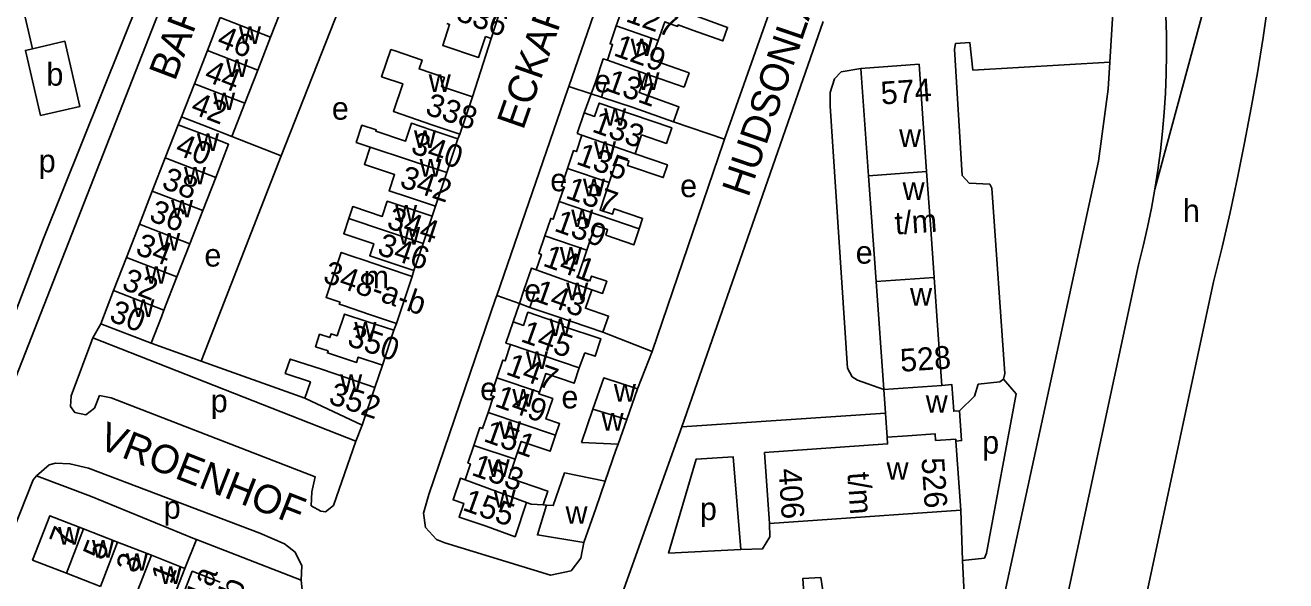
# Model space of a CAD drawing. Extents: x 159294 to 161936, y 384538 to 386517.
# Drawn here: x 161615.6 to 161836.9, y 385101 to 385198.5 of the extents above; entities that cross this region are included whole.
import ezdxf

# ---------------------------------------------------------------- set-up
doc = ezdxf.new("R2010")
doc.units = 0
for name, color, linetype in [('BLT_Basislijn', 7, 'Continuous'), ('BLT_Bebouwing', 7, 'Continuous'), ('BLT_Centroide', 7, 'Continuous'), ('BLT_Huisnummer', 7, 'Continuous'), ('BLT_Huisnummer_ tussenligend', 7, 'Continuous'), ('BLT_Huisnummer_reeks', 7, 'Continuous'), ('BLT_Onderdoorgang_en_onderverdeling', 7, 'Continuous'), ('BLT_Onderverdeling_panden', 7, 'Continuous'), ('BLT_Straatnaam', 7, 'Continuous'), ('BLT_Vlakafsluiter', 7, 'Continuous')]:
    doc.layers.add(name, color=color, linetype=linetype)

msp = doc.modelspace()

# ---------------------------------------------------------------- linework, layer by layer
at = {"layer": 'BLT_Basislijn'}
for p, q in [((161679.62, 385224.05), (161660.57, 385175.55)), ((161723.4, 385223.71), (161711.03, 385187.71)), ((161628.12, 385172.88), (161646.48, 385219.73)), ((161618.85, 385161.07), (161637.25, 385206.88)), ((161806.91, 385207.1), (161805.99, 385191.99)), ((161738.36, 385178.48), (161747.52, 385204.43)), ((161615.25, 385201.44), (161616.9, 385194.35)), ((161730.86, 385128.01), (161755.69, 385199.14)), ((161697.38, 385196.17), (161694.12, 385185.9)), ((161714.96, 385186.44), (161715.77, 385188.68)), ((161711.03, 385187.71), (161714.96, 385186.44)), ((161713.74, 385183.09), (161714.96, 385186.44)), ((161714.96, 385186.44), (161716.76, 385185.86)), ((161642.48, 385181.03), (161643.08, 385182.43)), ((161729.43, 385181.55), (161738.36, 385178.48)), ((161691.91, 385179.37), (161691.58, 385178.55)), ((161651.92, 385178.98), (161660.57, 385175.55)), ((161660.57, 385175.55), (161646.54, 385139.52)), ((161613.46, 385135.38), (161628.12, 385172.88)), ((161687.05, 385164.95), (161687.62, 385166.71)), ((161608.36, 385133.7), (161618.85, 385161.07)), ((161683.85, 385155.42), (161683.57, 385154.36)), ((161794.16, 385077.96), (161811, 385156.43)), ((161702.37, 385149.64), (161698.38, 385151.08)), ((161702.37, 385149.64), (161703.16, 385151.98)), ((161701.27, 385146.42), (161702.37, 385149.64)), ((161704.22, 385148.97), (161702.37, 385149.64)), ((161628.88, 385146.1), (161627.48, 385143.62)), ((161680.35, 385144.95), (161680.77, 385146.12)), ((161717.03, 385144.6), (161725.66, 385141.21)), ((161627.48, 385143.62), (161673.67, 385125.47)), ((161646.54, 385139.52), (161637.73, 385142.66)), ((161664.71, 385133.06), (161646.54, 385139.52)), ((161676.99, 385134.92), (161678.35, 385138.84)), ((161730.86, 385128.01), (161766.6, 385130.41)), ((161674.74, 385128.31), (161673.67, 385125.47)), ((161719.31, 385123.93), (161719.72, 385124.95)), ((161779.81, 385113.36), (161780.14, 385104.58)), ((161643.64, 385103.13), (161645.67, 385108.25)), ((161645.67, 385108.25), (161664.09, 385101.11)), ((161664.09, 385101.11), (161664.48, 385097.1))]:
    msp.add_line(p, q, dxfattribs=at)
for points in [[(161824.2, 385153.45), (161825.67, 385159.53), (161827.07, 385165.62), (161828.39, 385171.72), (161829.62, 385177.85), (161830.79, 385183.99), (161831.87, 385190.14), (161832.87, 385196.31), (161833.79, 385202.49), (161834.64, 385208.68), (161835.4, 385214.88), (161836.09, 385221.09), (161836.69, 385227.31), (161836.86, 385229.15)], [(161813.9, 385169.7), (161814.43, 385173.06), (161814.88, 385176.43), (161815.25, 385179.81), (161815.54, 385183.19), (161815.75, 385186.58), (161815.88, 385189.98), (161815.93, 385193.38), (161815.9, 385196.77), (161815.79, 385200.17), (161815.74, 385201.24)], [(161787.31, 385136.37), (161787.53, 385137.34), (161785.28, 385169.87), (161784.9, 385170.58), (161781.3, 385170.77), (161780.09, 385172.13), (161778.74, 385194.28), (161778.91, 385195.28), (161781.43, 385195.45), (161781.94, 385190.61), (161805.99, 385191.99)], [(161762.3, 385190.91), (161758.81, 385190.3), (161757.68, 385189.08), (161756.88, 385186.69), (161756.89, 385184.27), (161759.92, 385138.33)], [(161762.65, 384984.06), (161803.97, 385174.65), (161805.7, 385187.28), (161805.99, 385191.99)], [(161698.38, 385151.08), (161710.88, 385187.27), (161711.03, 385187.71)], [(161738.36, 385178.48), (161738.18, 385177.95), (161725.66, 385141.21)], [(161811, 385156.43), (161811.84, 385159.73), (161812.61, 385163.04), (161813.29, 385166.36), (161813.9, 385169.7)], [(161796.66, 385024.4), (161812.3, 385097.98), (161824.2, 385153.45)], [(161713.65, 385107.71), (161713.17, 385104.94), (161711.42, 385102.71), (161707.83, 385101.95), (161689.26, 385107.64), (161687.83, 385108.22), (161685.87, 385110.36), (161685.54, 385112.86), (161686.46, 385116.15), (161698.17, 385150.46), (161698.38, 385151.08)], [(161627.48, 385143.62), (161623.69, 385133.43), (161623.56, 385131.55), (161624.33, 385130.54), (161626.29, 385130.1), (161627.78, 385131.27), (161628.68, 385133.49), (161630.73, 385133.07), (161666.52, 385119.25), (161665.93, 385116.59), (161665.82, 385114.15), (161667.5, 385113.2), (161668.33, 385113.1), (161669.76, 385114.23), (161673.67, 385125.47)], [(161725.66, 385141.21), (161723.09, 385134.7)], [(161759.92, 385138.33), (161760.78, 385136.81), (161761.67, 385136.17), (161766.31, 385134.54)], [(161779.59, 385130.81), (161782.25, 385133.4), (161782.89, 385135.47), (161786.68, 385135.89), (161787.31, 385136.37)], [(161780.14, 385104.58), (161783.97, 385104.97), (161784.34, 385105.82), (161789.56, 385133.79), (161787.31, 385136.37)], [(161730.86, 385128.01), (161719.85, 385097.24), (161716.35, 385083.92), (161705.65, 385033.01)], [(161719.31, 385123.93), (161717.42, 385118.49)], [(161741.25, 385106.46), (161739.87, 385122.75), (161733.38, 385122.32), (161728.55, 385105.86), (161741.25, 385106.46)], [(161617.59, 385119.41), (161619.86, 385121.35), (161620.95, 385121.61), (161623.49, 385121.54), (161626.76, 385120.78), (161656.79, 385109.37), (161661.11, 385107.48), (161662.99, 385106.02), (161664.16, 385103.64), (161664.09, 385101.11)], [(161607.82, 385095.65), (161617.01, 385118.7), (161617.59, 385119.41)], [(161645.67, 385108.25), (161645.37, 385108.37), (161627.09, 385115.85), (161617.59, 385119.41)], [(161706.53, 385114.31), (161707.14, 385114.28)], [(161741.25, 385106.46), (161745.04, 385106.61), (161746.29, 385108.73), (161746.26, 385111.04)], [(161752.52, 385095.33), (161752.11, 385101.41), (161755.25, 385101.54), (161755.95, 385096.94), (161780.13, 385098.66), (161780.4, 385098.74), (161780.14, 385104.58)]]:
    msp.add_lwpolyline(points, dxfattribs=at)
at = {"layer": 'BLT_Bebouwing'}
for p, q in [((161660.95, 385202.18), (161658.69, 385196.38)), ((161699.18, 385201.59), (161697.38, 385196.17)), ((161649.87, 385199.82), (161647.6, 385194.02)), ((161658.69, 385196.38), (161656.43, 385190.58)), ((161647.6, 385194.02), (161645.34, 385188.22)), ((161656.43, 385190.58), (161654.18, 385184.78)), ((161763.64, 385172.08), (161762.3, 385190.91)), ((161645.34, 385188.22), (161643.08, 385182.43)), ((161724.55, 385189.98), (161731.25, 385187.64)), ((161694.12, 385185.9), (161691.91, 385179.37)), ((161654.18, 385184.78), (161651.92, 385178.98)), ((161713.74, 385183.09), (161712.51, 385179.48)), ((161773.82, 385172.8), (161773.17, 385182.09)), ((161642.48, 385181.03), (161640.21, 385175.21)), ((161712.51, 385179.48), (161713.34, 385179.2)), ((161691.58, 385178.55), (161689.6, 385172.63)), ((161640.21, 385175.21), (161637.94, 385169.39)), ((161689.6, 385172.63), (161687.62, 385166.71)), ((161774.48, 385163.51), (161773.82, 385172.8)), ((161646.8, 385165.94), (161649.06, 385171.77)), ((161764.96, 385153.52), (161763.64, 385172.08)), ((161637.94, 385169.39), (161635.68, 385163.57)), ((161644.53, 385160.12), (161646.8, 385165.94)), ((161687.05, 385164.95), (161685.45, 385160.18)), ((161635.68, 385163.57), (161633.41, 385157.74)), ((161775.13, 385154.24), (161774.48, 385163.51)), ((161642.26, 385154.3), (161644.53, 385160.12)), ((161685.45, 385160.18), (161683.85, 385155.42)), ((161633.41, 385157.74), (161631.14, 385151.92)), ((161639.99, 385148.48), (161642.26, 385154.3)), ((161683.57, 385154.36), (161680.77, 385146.12)), ((161764.96, 385153.52), (161766.31, 385134.54)), ((161775.78, 385144.98), (161775.13, 385154.24)), ((161631.14, 385151.92), (161628.88, 385146.1)), ((161628.88, 385146.1), (161637.73, 385142.66)), ((161680.35, 385144.95), (161678.35, 385138.84)), ((161776.47, 385135.28), (161775.78, 385144.98)), ((161674.74, 385128.31), (161664.71, 385133.06)), ((161676.99, 385134.92), (161674.74, 385128.31)), ((161721.23, 385129.31), (161723.09, 385134.7)), ((161766.31, 385134.54), (161766.6, 385130.41)), ((161719.72, 385124.95), (161721.23, 385129.31)), ((161713.24, 385125.28), (161719.72, 385124.95)), ((161779.81, 385113.36), (161778.96, 385125.51)), ((161745.39, 385123.53), (161746.26, 385111.04)), ((161715.77, 385113.69), (161717.42, 385118.49)), ((161713.65, 385107.71), (161715.77, 385113.69)), ((161771.42, 385112.78), (161779.81, 385113.36)), ((161746.26, 385111.04), (161754.65, 385111.62)), ((161754.65, 385111.62), (161763.03, 385112.2)), ((161763.03, 385112.2), (161771.42, 385112.78)), ((161631.83, 385107.77), (161625.89, 385110.08)), ((161637.77, 385105.47), (161631.83, 385107.77)), ((161643.64, 385103.13), (161637.77, 385105.47)), ((161622.88, 385102.32), (161628.82, 385100.01)), ((161639.51, 385092.59), (161643.64, 385103.13))]:
    msp.add_line(p, q, dxfattribs=at)
for points in [[(161721.94, 385204.14), (161720.93, 385201.32), (161720.45, 385201.49), (161719.36, 385198.36)], [(161726.69, 385195.81), (161727.86, 385199.08), (161730.11, 385198.28), (161730.2, 385198.53), (161732.76, 385197.62), (161738.06, 385195.73), (161738.9, 385198.1), (161733.61, 385199.99)], [(161696.42, 385196.48), (161695.21, 385192.83), (161688.9, 385194.91), (161690.12, 385198.62), (161689.65, 385198.76)], [(161719.36, 385198.36), (161718.27, 385195.24), (161718.71, 385195.09), (161717.8, 385192.33)], [(161616.9, 385194.35), (161622.61, 385195.66), (161625.23, 385184.24), (161618.29, 385182.65)], [(161697.38, 385196.17), (161696.79, 385196.36), (161696.42, 385196.48)], [(161731.25, 385187.64), (161732.14, 385190.11), (161725.5, 385192.48), (161726.69, 385195.81)], [(161618.29, 385182.65), (161615.67, 385194.07), (161616.9, 385194.35)], [(161694.12, 385185.9), (161688.68, 385187.74), (161689.21, 385189.31), (161684.76, 385190.82), (161685.29, 385192.36), (161680.55, 385193.96), (161679.8, 385194.22), (161678.19, 385189.45), (161681.89, 385188.2), (161680.24, 385183.35), (161687.17, 385180.97), (161691.91, 385179.37)], [(161717.8, 385192.33), (161717.05, 385192.57), (161715.77, 385188.68)], [(161773.17, 385182.09), (161772.5, 385191.63), (161762.3, 385190.91)], [(161715.77, 385188.68), (161717.5, 385188.11), (161716.76, 385185.86)], [(161729.43, 385181.55), (161730.37, 385184.14), (161723.36, 385186.7), (161724.55, 385189.98)], [(161716.76, 385185.86), (161722.35, 385184.04), (161729.43, 385181.55)], [(161722.67, 385175.9), (161723.81, 385179.23), (161728.15, 385177.75), (161729.09, 385180.49), (161722.03, 385182.89), (161716.37, 385184.82), (161715.56, 385182.47), (161713.74, 385183.09)], [(161643.08, 385182.43), (161647.74, 385180.61), (161651.92, 385178.98)], [(161649.06, 385171.77), (161651.33, 385177.59), (161647.14, 385179.22), (161642.48, 385181.03)], [(161676.18, 385177.11), (161673.73, 385177.93), (161674.73, 385180.94), (161677.25, 385180.1), (161677.18, 385179.87), (161682.38, 385178.14), (161683.42, 385181.28), (161686.84, 385180.14), (161691.58, 385178.55)], [(161687.62, 385166.71), (161682.88, 385168.29), (161679.5, 385169.42), (161680.45, 385172.28), (161675.16, 385174.05), (161676.18, 385177.11)], [(161713.34, 385179.2), (161712.36, 385176.31), (161711.88, 385176.47), (161710.82, 385173.34)], [(161718.11, 385170.86), (161719.63, 385175.33), (161721.58, 385174.67), (161721.31, 385173.88), (161727.6, 385171.75), (161728.35, 385173.97), (161722.67, 385175.9)], [(161710.82, 385173.34), (161709.75, 385170.22), (161710.23, 385170.06), (161709.37, 385167.55)], [(161723.38, 385162.78), (161723.99, 385164.57), (161719.02, 385166.27), (161718.69, 385165.3), (161716.53, 385166.04), (161718.11, 385170.86)], [(161672.42, 385164.56), (161673.13, 385166.66), (161678.28, 385164.93), (161679.18, 385167.59), (161682.31, 385166.54), (161687.05, 385164.95)], [(161709.37, 385167.55), (161708.31, 385164.43), (161707.85, 385164.58), (161706.8, 385161.51)], [(161683.85, 385155.42), (161679.11, 385157.01), (161676.09, 385158.02), (161676.79, 385160.12), (161671.53, 385161.89), (161672.42, 385164.56)], [(161714.17, 385159), (161715.66, 385163.35), (161717.85, 385162.61), (161717.51, 385161.62)], [(161717.51, 385161.62), (161722.44, 385159.94), (161723.38, 385162.78)], [(161706.8, 385161.51), (161705.76, 385158.43), (161706.23, 385158.27), (161705.31, 385155.55)], [(161683.57, 385154.36), (161678.84, 385155.97), (161674.95, 385157.29), (161673.11, 385157.92), (161671.11, 385158.6), (161668.43, 385150.71), (161670.88, 385149.87), (161670.76, 385149.52), (161671.48, 385149.28), (161676.04, 385147.73), (161680.77, 385146.12)], [(161715.05, 385152.06), (161716.95, 385151.41), (161717.68, 385153.55), (161715.02, 385154.46), (161714.73, 385153.6), (161712.59, 385154.33), (161714.17, 385159)], [(161705.31, 385155.55), (161704.48, 385155.84), (161703.16, 385151.98)], [(161703.16, 385151.98), (161705.03, 385151.34), (161704.22, 385148.97)], [(161717.03, 385144.6), (161718, 385147.45), (161713.94, 385148.83), (161715.05, 385152.06)], [(161637.73, 385142.66), (161639.54, 385147.32), (161639.99, 385148.48)], [(161704.22, 385148.97), (161708.95, 385147.35), (161717.03, 385144.6)], [(161678.35, 385138.84), (161674.09, 385140.24), (161673.79, 385139.31), (161669.04, 385140.87), (161668.68, 385140.99), (161668.79, 385141.32), (161666.59, 385142.05), (161667.31, 385144.24), (161669.1, 385143.66), (161669.32, 385144.33), (161670.4, 385143.98), (161671.65, 385147.8), (161675.6, 385146.51), (161680.35, 385144.95)], [(161701.27, 385146.42), (161700.01, 385142.7), (161700.81, 385142.43)], [(161712.88, 385138.35), (161713.86, 385140.97), (161715.63, 385140.38), (161716.66, 385143.43), (161709.94, 385145.7), (161710.04, 385146.02), (161708.6, 385146.51), (161703.86, 385148.11), (161703.08, 385145.81), (161701.27, 385146.42)], [(161700.81, 385142.43), (161699.84, 385139.57), (161699.43, 385139.71), (161698.38, 385136.61)], [(161664.71, 385133.06), (161665.68, 385135.88), (161661.28, 385137.38), (161662.14, 385139.91), (161667.62, 385138.11), (161672.26, 385136.53), (161676.99, 385134.92)], [(161705.88, 385134.08), (161706.98, 385137.35), (161711.96, 385135.66), (161712.88, 385138.35)], [(161698.38, 385136.61), (161697.34, 385133.52), (161697.82, 385133.36), (161696.86, 385130.53)], [(161723.09, 385134.7), (161717.17, 385136.59), (161715.26, 385131.1)], [(161779.59, 385130.81), (161778.59, 385130.74), (161778.26, 385135.41), (161776.47, 385135.28)], [(161708.72, 385126.52), (161709.42, 385128.58), (161707.02, 385129.39), (161708.22, 385132.95), (161705.78, 385133.78), (161705.88, 385134.08)], [(161715.26, 385131.1), (161713.24, 385125.28)], [(161778.96, 385125.51), (161779.96, 385125.58), (161779.59, 385130.81)], [(161696.86, 385130.53), (161695.91, 385127.7), (161695.43, 385127.87), (161694.38, 385124.76)], [(161766.6, 385130.41), (161766.9, 385126.2)], [(161701.62, 385122.31), (161702.68, 385125.46), (161707.78, 385123.73), (161708.72, 385126.52)], [(161766.9, 385126.2), (161766.99, 385125.02), (161745.39, 385123.53)], [(161694.38, 385124.76), (161693.33, 385121.64), (161693.77, 385121.5), (161692.83, 385118.71)], [(161706.53, 385114.31), (161707.35, 385116.73), (161700.51, 385119.04), (161701.62, 385122.31)], [(161707.14, 385114.28), (161708.31, 385114.2), (161710.25, 385119.92), (161717.42, 385118.49)], [(161692.83, 385118.71), (161692, 385118.99), (161690.72, 385115.2), (161692.59, 385114.57), (161691.78, 385112.18), (161696.52, 385110.58), (161701.6, 385108.72), (161703.62, 385114.75)], [(161703.62, 385114.75), (161704.41, 385114.45), (161706.53, 385114.31)], [(161707.14, 385114.28), (161705.51, 385109.05), (161713.65, 385107.71)], [(161625.89, 385110.08), (161619.96, 385112.39), (161616.94, 385104.63), (161622.88, 385102.32)], [(161649.84, 385100.73), (161644.94, 385102.67), (161642.24, 385095.7), (161647.1, 385093.79)]]:
    msp.add_lwpolyline(points, dxfattribs=at)
at = {"layer": 'BLT_Onderdoorgang_en_onderverdeling'}
for p, q in [((161766.31, 385134.54), (161776.47, 385135.28)), ((161778.96, 385125.51), (161778.94, 385125.85))]:
    msp.add_line(p, q, dxfattribs=at)
msp.add_lwpolyline([(161778.94, 385125.85), (161775.39, 385125.61), (161775.31, 385126.79), (161770.47, 385126.45)], dxfattribs=at)
at = {"layer": 'BLT_Onderverdeling_panden'}
for p, q in [((161658.69, 385196.38), (161649.87, 385199.82)), ((161719.36, 385198.36), (161726.69, 385195.81)), ((161656.43, 385190.58), (161647.6, 385194.02)), ((161717.8, 385192.33), (161724.55, 385189.98)), ((161654.18, 385184.78), (161645.34, 385188.22)), ((161689.6, 385172.63), (161676.18, 385177.11)), ((161713.34, 385179.2), (161722.67, 385175.9)), ((161649.06, 385171.77), (161640.21, 385175.21)), ((161710.82, 385173.34), (161718.11, 385170.86)), ((161763.64, 385172.08), (161773.82, 385172.8)), ((161646.8, 385165.94), (161637.94, 385169.39)), ((161709.37, 385167.55), (161723.38, 385162.78)), ((161685.45, 385160.18), (161672.42, 385164.56)), ((161644.53, 385160.12), (161635.68, 385163.57)), ((161706.8, 385161.51), (161714.17, 385159)), ((161642.26, 385154.3), (161633.41, 385157.74)), ((161705.31, 385155.55), (161715.05, 385152.06)), ((161764.96, 385153.52), (161775.13, 385154.24)), ((161639.99, 385148.48), (161631.14, 385151.92)), ((161700.81, 385142.43), (161712.88, 385138.35)), ((161698.38, 385136.61), (161705.88, 385134.08)), ((161715.26, 385131.1), (161721.23, 385129.31)), ((161696.86, 385130.53), (161708.72, 385126.52)), ((161770.47, 385126.45), (161766.9, 385126.2)), ((161694.38, 385124.76), (161701.62, 385122.31)), ((161692.83, 385118.71), (161703.62, 385114.75)), ((161622.88, 385102.32), (161625.89, 385110.08)), ((161628.82, 385100.01), (161631.83, 385107.77)), ((161634.76, 385097.71), (161637.77, 385105.47))]:
    msp.add_line(p, q, dxfattribs=at)
at = {"layer": 'BLT_Vlakafsluiter'}
msp.add_lwpolyline([(161822.78, 385203.09), (161822.68, 385202.07), (161813.9, 385169.7)], dxfattribs=at)

# ---------------------------------------------------------------- texts
at = {"layer": 'BLT_Centroide'}
for s, p in [('w', (161653.15, 385195.19)), ('w', (161721.88, 385193.06)), ('b', (161619.36, 385187.88)), ('w', (161650.88, 385189.41)), ('w', (161686.45, 385186.78)), ('e', (161715.48, 385186.69)), ('w', (161723.08, 385187.14)), ('w', (161648.62, 385183.59)), ('e', (161669.45, 385181.9)), ('w', (161717.23, 385180.84)), ('w', (161645.77, 385176.41)), ('w', (161683.86, 385176.94)), ('w', (161769, 385177.14)), ('w', (161715.46, 385175.03)), ('p', (161618.01, 385172.68)), ('w', (161684.84, 385171.91)), ('w', (161643.5, 385170.56)), ('e', (161707.78, 385169.34)), ('w', (161713.52, 385168.47)), ('e', (161730.57, 385168.31)), ('w', (161769.61, 385167.83)), ('w', (161641.23, 385164.75)), ('w', (161680.56, 385163.88)), ('w', (161711.45, 385163.06)), ('h', (161818.8, 385163.93)), ('w', (161638.97, 385158.94)), ('w', (161681.07, 385160)), ('w', (161709.46, 385156.47)), ('e', (161761.38, 385156.64)), ('e', (161647.08, 385156.13)), ('w', (161636.7, 385153.12)), ('m', (161675.02, 385152.31)), ('e', (161703.21, 385149.94)), ('w', (161710.58, 385150.22)), ('w', (161770.92, 385149.28)), ('w', (161634.44, 385147.28)), ('w', (161673.41, 385143.31)), ('w', (161707.62, 385143.94)), ('w', (161703.51, 385138.16)), ('w', (161670.9, 385134.12)), ('e', (161695.47, 385132.69)), ('w', (161718.94, 385132.44)), ('p', (161648.2, 385130.57)), ('w', (161701.12, 385131.56)), ('e', (161709.74, 385131.24)), ('w', (161773.67, 385130.47)), ('w', (161698.78, 385125.88)), ('w', (161716.79, 385127.35)), ('p', (161783.58, 385123.3)), ('w', (161696.79, 385119.22)), ('w', (161766.8, 385118.73)), ('w', (161697.83, 385113.84)), ('p', (161639.95, 385111.89)), ('w', (161710.46, 385111)), ('p', (161734.04, 385111.64)), ('w', (161621.42, 385107.34)), ('w', (161627.36, 385105.05)), ('w', (161633.3, 385102.75)), ('w', (161639.23, 385100.44))]:
    msp.add_text(s, height=4, dxfattribs=at).set_placement(p)
at = {"layer": 'BLT_Huisnummer'}
for s, rotation, p in [('336', 339.9065, (161691, 385199.45)), ('46', 338.7295, (161649.06, 385194.82)), ('131', 340.39, (161717.33, 385187.09)), ('42', 338.7295, (161644.47, 385183.14)), ('338', 341.3114, (161685.65, 385182.91)), ('133', 340.39, (161714.92, 385179.86)), ('340', 341.3114, (161683.11, 385176.12)), ('40', 338.7295, (161641.77, 385175.94)), ('342', 341.3114, (161681.16, 385170.17)), ('137', 340.39, (161710.27, 385168.23)), ('344', 341.3114, (161678.88, 385162.98)), ('34', 338.7295, (161634.78, 385158.4)), ('346', 341.3114, (161677.22, 385158.33)), ('143', 340.39, (161704.69, 385150.19)), ('30', 338.7295, (161630.18, 385146.67)), ('145', 340.39, (161702.4, 385143.05)), ('350', 341.3114, (161671.95, 385142.34)), ('352', 341.1773, (161668.67, 385132.17)), ('149', 340.39, (161697.85, 385131.68)), ('155', 340.39, (161692.19, 385113.46)), ('7', 68.7634, (161623.46, 385106.68)), ('1', 68.7659, (161641.27, 385100.23)), ('1a', 68.7659, (161647.33, 385096.95)), ('1b', 68.7659, (161652.21, 385095.02))]:
    msp.add_text(s, height=4, rotation=rotation, dxfattribs=at).set_placement(p)
at = {"layer": 'BLT_Huisnummer_ tussenligend'}
for s, rotation, p in [('127', 340.39, (161720.84, 385199.21)), ('129', 340.39, (161718.7, 385193.23)), ('44', 338.7295, (161646.85, 385188.83)), ('135', 340.39, (161712.14, 385174.18)), ('38', 338.7295, (161639.38, 385169.97)), ('36', 338.7295, (161637.17, 385164.27)), ('139', 340.39, (161708.29, 385162.45)), ('141', 340.39, (161706.31, 385156.32)), ('32', 338.7295, (161632.38, 385152.24)), ('147', 340.39, (161699.8, 385137.28)), ('151', 340.39, (161695.89, 385125.54)), ('153', 340.39, (161693.77, 385119.61)), ('5', 68.7659, (161629.35, 385104.39)), ('3', 68.7659, (161635.13, 385102.1))]:
    msp.add_text(s, height=4, rotation=rotation, dxfattribs=at).set_placement(p)
at = {"layer": 'BLT_Huisnummer_reeks'}
for s, rotation, p in [('574', 4.0127, (161765.91, 385184.56)), ('t/m', 4.0281, (161768.37, 385161.74)), ('348-a-b', 341.2229, (161667.69, 385153.47)), ('528', 4.0276, (161769.31, 385137.65)), ('526', 273.9715, (161772.9, 385122.5)), ('406', 273.9712, (161747.82, 385120.61)), ('t/m', 273.9715, (161759.93, 385119.93))]:
    msp.add_text(s, height=4, rotation=rotation, dxfattribs=at).set_placement(p)
at = {"layer": 'BLT_Straatnaam'}
for s, rotation, p in [('ECKARTSEWEG ZUID', 70.7098, (161703.02, 385179.95)), ('BAFFINLAAN', 69.2683, (161641.9, 385188.53)), ('HUDSONLAAN', 71.1277, (161742.53, 385168.13)), ('VROENHOF', 338.6397, (161628.2, 385124.35))]:
    msp.add_text(s, height=5, rotation=rotation, dxfattribs=at).set_placement(p)

doc.saveas('drawing.dxf')
